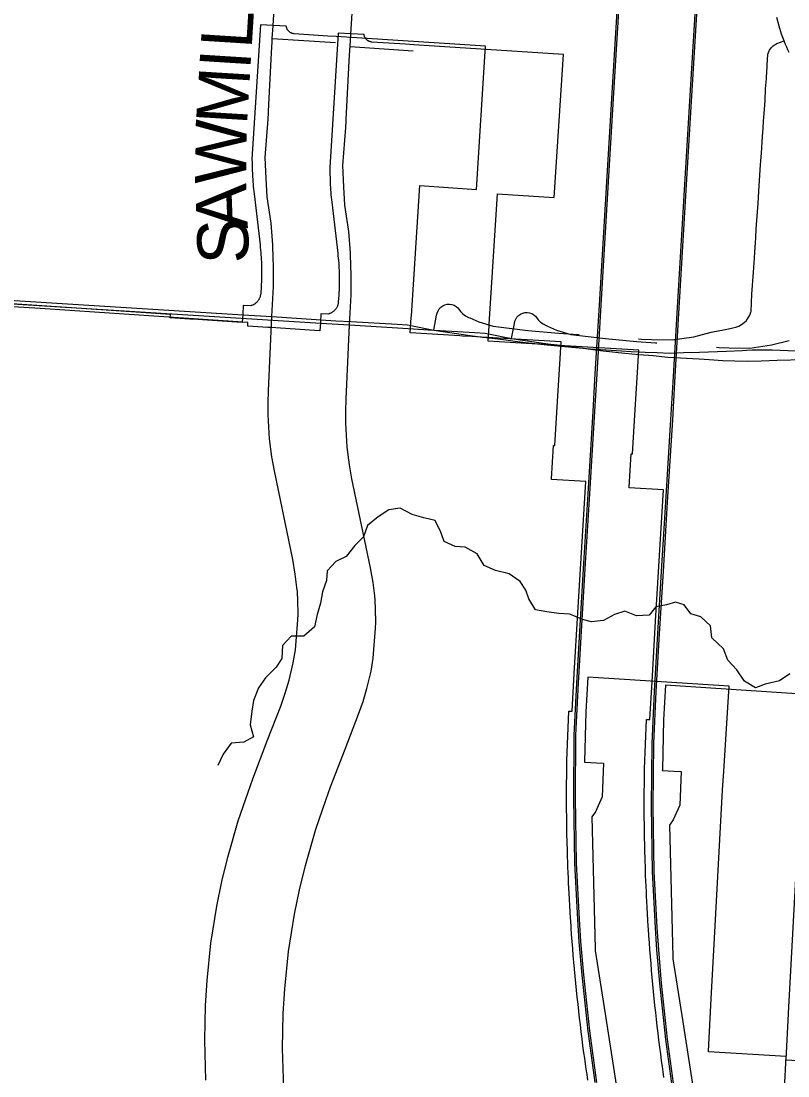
# Model space of a CAD drawing. Extents: x -38.2 to 41.9, y -4 to 24.9.
# Drawn here: x 5.806 to 6.659, y 19.427 to 20.6 of the extents above; entities that cross this region are included whole.
import ezdxf

# ---------------------------------------------------------------- set-up
doc = ezdxf.new("R2010")
doc.units = 0
for name, color, linetype in [('Default', 7, 'Continuous'), ('GM_X_County_Road', 7, 'Continuous'), ('GM_X_County_Road_Text', 7, 'Continuous'), ('GM_X_Minor_River', 7, 'Continuous'), ('GM_X_Rail_Line', 7, 'Continuous'), ('GM_X_Rail_Line_Text', 7, 'Continuous'), ('GM_X_State_Location', 7, 'Continuous'), ('GM_X_Township_Road', 7, 'Continuous'), ('GM_X_Township_Road_Text', 7, 'Continuous')]:
    doc.layers.add(name, color=color, linetype=linetype)

msp = doc.modelspace()

# ---------------------------------------------------------------- linework, layer by layer
at = {"layer": 'Default'}
for points in [[(6.4368, 19.422), (6.4359, 19.4282), (6.435, 19.4343), (6.4341, 19.4404), (6.4333, 19.4465), (6.4325, 19.4526), (6.4314, 19.4603), (6.4304, 19.4681), (6.4295, 19.4758), (6.4285, 19.4835), (6.4276, 19.4912), (6.4267, 19.499), (6.4259, 19.5067), (6.425, 19.5144), (6.4242, 19.5222), (6.4234, 19.5299), (6.4227, 19.5377), (6.422, 19.5454), (6.4213, 19.5532), (6.4206, 19.5609), (6.42, 19.5687), (6.4194, 19.5764), (6.4188, 19.5842), (6.4183, 19.592), (6.4177, 19.5997), (6.4176, 19.6023), (6.4171, 19.6093), (6.4167, 19.6162), (6.4163, 19.6232), (6.416, 19.6302), (6.4157, 19.6357), (6.4154, 19.6413), (6.4152, 19.6469), (6.4149, 19.653), (6.4147, 19.6591), (6.4144, 19.6653), (6.4143, 19.6697), (6.4141, 19.6742), (6.414, 19.6797), (6.4139, 19.6845), (6.4137, 19.6892), (6.4136, 19.6939), (6.4134, 19.7004), (6.4131, 19.7378), (6.4134, 19.7752), (6.4135, 19.7775), (6.4155, 19.8326), (6.4193, 19.8324), (6.4217, 19.8744), (6.4257, 19.9418), (6.4346, 20.0881), (6.3963, 20.0904), (6.3964, 20.0911), (6.3986, 20.1282), (6.4001, 20.1281), (6.4037, 20.1894), (6.4051, 20.2126), (6.407, 20.2434), (6.3183, 20.2487), (6.3076, 20.2493), (6.2973, 20.2499), (6.2945, 20.2501), (6.2639, 20.2518), (6.2393, 20.2533), (6.2404, 20.2705), (6.2405, 20.2722), (6.2498, 20.4174), (6.313, 20.4131), (6.3231, 20.5724), (6.1569, 20.583), (6.1476, 20.5836), (6.1101, 20.5862), (6.1096, 20.5862), (6.1091, 20.5863), (6.1086, 20.5864), (6.108, 20.5865), (6.1075, 20.5867), (6.107, 20.5869), (6.1066, 20.5871), (6.1061, 20.5874), (6.1056, 20.5876), (6.1052, 20.5879), (6.1048, 20.5883), (6.1044, 20.5886), (6.104, 20.589), (6.1036, 20.5894), (6.1033, 20.5898), (6.103, 20.5902), (6.1027, 20.5907), (6.1024, 20.5911), (6.1022, 20.5916), (6.1019, 20.5921), (6.1018, 20.5926), (6.1016, 20.5931), (6.1015, 20.5936), (6.1013, 20.5947), (6.0726, 20.5961), (6.0631, 20.4466), (6.0632, 20.4433), (6.0633, 20.4395), (6.0635, 20.4348), (6.0637, 20.4301), (6.0637, 20.4299), (6.0638, 20.4272), (6.0639, 20.4244), (6.0641, 20.4217), (6.0643, 20.419), (6.0645, 20.4163), (6.0648, 20.4135), (6.0651, 20.4108), (6.0654, 20.4081), (6.0721, 20.3512), (6.0724, 20.3485), (6.0726, 20.3458), (6.0729, 20.343), (6.0731, 20.3403), (6.0733, 20.3376), (6.0734, 20.3349), (6.0736, 20.3321), (6.0737, 20.3294), (6.0737, 20.3267), (6.0738, 20.3239), (6.0738, 20.3212), (6.0738, 20.3185), (6.0737, 20.3158), (6.0737, 20.313), (6.0736, 20.3103), (6.0734, 20.3076), (6.0733, 20.3048), (6.0728, 20.2968), (6.0727, 20.2962), (6.0726, 20.2955), (6.0724, 20.2948), (6.0723, 20.2942), (6.0721, 20.2935), (6.0719, 20.2929), (6.0716, 20.2922), (6.0713, 20.2916), (6.071, 20.291), (6.0707, 20.2904), (6.0703, 20.2898), (6.0699, 20.2893), (6.0695, 20.2887), (6.0691, 20.2882), (6.0686, 20.2877), (6.0682, 20.2872), (6.0677, 20.2868), (6.0672, 20.2863), (6.0666, 20.2859), (6.0661, 20.2855), (6.0655, 20.2852), (6.0649, 20.2848), (6.0643, 20.2845), (6.0637, 20.2842), (6.0631, 20.284), (6.0624, 20.2837), (6.0618, 20.2835), (6.0617, 20.2835), (6.0533, 20.2838), (6.0528, 20.2743), (6.0521, 20.2648), (6.0463, 20.2652), (5.9975, 20.2685), (5.9941, 20.2687), (5.972, 20.2702), (5.9723, 20.274), (5.7408, 20.2896)], [(6.6556, 19.4121), (6.6576, 19.4485), (6.5709, 19.4535), (6.5709, 19.4542), (6.574, 19.5125), (6.5777, 19.5802), (6.5865, 19.7446), (6.588, 19.7657), (6.594, 19.8602), (6.4368, 19.8705), (6.4345, 19.832), (6.4332, 19.7767), (6.4332, 19.7759), (6.4463, 19.7751), (6.4541, 19.7746), (6.4527, 19.7373), (6.4453, 19.7207), (6.4412, 19.715), (6.4448, 19.5684), (6.445, 19.5662), (6.4559, 19.496), (6.491, 19.2712)]]:
    msp.add_lwpolyline(points, dxfattribs=at)
at = {"layer": 'GM_X_County_Road'}
for p, q in [((6.0866, 20.5949), (6.0898, 20.6465)), ((6.0533, 20.2735), (6.0851, 20.2715))]:
    msp.add_line(p, q, dxfattribs=at)
for points in [[(6.0855, 20.5772), (6.0857, 20.581), (6.0866, 20.5949)], [(6.6607, 20.5655), (6.6594, 20.5684), (6.6581, 20.5712), (6.6568, 20.5741), (6.6556, 20.5771), (6.6551, 20.5783), (6.6545, 20.58), (6.6524, 20.5859), (6.6497, 20.5946), (6.6472, 20.6042)], [(6.5215, 19.4251), (6.5206, 19.4312), (6.5198, 19.4373), (6.5189, 19.4434), (6.5179, 19.4512), (6.5169, 19.4589), (6.5159, 19.4666), (6.515, 19.4743), (6.5141, 19.4821), (6.5132, 19.4898), (6.5123, 19.4975), (6.5115, 19.5053), (6.5107, 19.513), (6.5099, 19.5207), (6.5092, 19.5285), (6.5085, 19.5362), (6.5078, 19.544), (6.5071, 19.5517), (6.5065, 19.5595), (6.5059, 19.5673), (6.5053, 19.575), (6.5047, 19.5828), (6.5042, 19.5905), (6.504, 19.5931), (6.5036, 19.6001), (6.5032, 19.607), (6.5028, 19.614), (6.5024, 19.621), (6.5021, 19.6266), (6.5019, 19.6321), (6.5016, 19.6377), (6.5014, 19.6438), (6.5011, 19.6499), (6.5009, 19.6561), (6.5008, 19.6605), (6.5006, 19.665), (6.5005, 19.6705), (6.5003, 19.6753), (6.5002, 19.68), (6.5001, 19.6847), (6.4999, 19.6912), (6.4995, 19.7286), (6.4999, 19.766), (6.5, 19.7683), (6.502, 19.8234), (6.5057, 19.8233), (6.5082, 19.8652), (6.5122, 19.9326), (6.521, 20.0789), (6.4828, 20.0812), (6.4829, 20.0819), (6.4851, 20.119), (6.4866, 20.1189), (6.4902, 20.1802), (6.4916, 20.2035), (6.4934, 20.2342), (6.4048, 20.2395), (6.3941, 20.2401), (6.3838, 20.2408), (6.3809, 20.2409), (6.3504, 20.2426), (6.3258, 20.2442), (6.3269, 20.2613), (6.327, 20.263), (6.3363, 20.4082), (6.3995, 20.4039), (6.4096, 20.5632), (6.2433, 20.5738), (6.2341, 20.5745), (6.1966, 20.577), (6.1961, 20.577), (6.1956, 20.5771), (6.195, 20.5772), (6.1945, 20.5774), (6.194, 20.5775), (6.1935, 20.5777), (6.193, 20.5779), (6.1926, 20.5782), (6.1921, 20.5785), (6.1917, 20.5788), (6.1912, 20.5791), (6.1908, 20.5794), (6.1905, 20.5798), (6.1901, 20.5802), (6.1897, 20.5806), (6.1894, 20.581), (6.1891, 20.5815), (6.1889, 20.5819), (6.1886, 20.5824), (6.1884, 20.5829), (6.1882, 20.5834), (6.1881, 20.5839), (6.188, 20.5844), (6.1878, 20.5855), (6.1591, 20.5869), (6.1496, 20.4374), (6.1497, 20.4341), (6.1498, 20.4303), (6.15, 20.4256), (6.1501, 20.4209), (6.1501, 20.4207), (6.1503, 20.418), (6.1504, 20.4153), (6.1506, 20.4125), (6.1508, 20.4098), (6.151, 20.4071), (6.1513, 20.4044), (6.1516, 20.4016), (6.1519, 20.3989), (6.1585, 20.342), (6.1588, 20.3393), (6.1591, 20.3366), (6.1594, 20.3338), (6.1596, 20.3311), (6.1598, 20.3284), (6.1599, 20.3257), (6.1601, 20.3229), (6.1602, 20.3202), (6.1602, 20.3175), (6.1603, 20.3148), (6.1603, 20.312), (6.1603, 20.3093), (6.1602, 20.3066), (6.1601, 20.3038), (6.16, 20.3011), (6.1599, 20.2984), (6.1597, 20.2957), (6.1592, 20.2876), (6.1592, 20.287), (6.159, 20.2863), (6.1589, 20.2856), (6.1587, 20.285), (6.1586, 20.2843), (6.1583, 20.2837), (6.1581, 20.283), (6.1578, 20.2824), (6.1575, 20.2818), (6.1572, 20.2812), (6.1568, 20.2807), (6.1564, 20.2801), (6.156, 20.2796), (6.1556, 20.279), (6.1551, 20.2785), (6.1546, 20.278), (6.1541, 20.2776), (6.1536, 20.2771), (6.1531, 20.2767), (6.1525, 20.2763), (6.152, 20.276), (6.1514, 20.2756), (6.1508, 20.2753), (6.1502, 20.275), (6.1495, 20.2748), (6.1489, 20.2746), (6.1482, 20.2744), (6.1482, 20.2743), (6.1398, 20.2746), (6.1392, 20.2651), (6.1386, 20.2556), (6.1328, 20.256), (6.084, 20.2593), (6.0806, 20.2595), (6.0585, 20.261), (6.0587, 20.2648), (5.8273, 20.2804), (5.7607, 20.2848)], [(6.0814, 20.4982), (6.0815, 20.5), (6.0847, 20.5648), (6.0855, 20.5772)], [(6.0863, 20.3505), (6.0862, 20.3515), (6.0843, 20.3753), (6.0801, 20.4047), (6.0788, 20.4251), (6.0778, 20.4487), (6.081, 20.491), (6.0814, 20.4982)], [(6.0851, 20.2715), (6.087, 20.3049), (6.0871, 20.3264), (6.0864, 20.3496), (6.0863, 20.3505)], [(5.3465, 20.3178), (5.3586, 20.3172), (5.4553, 20.3108), (6.0533, 20.2735)], [(6.0119, 19.4219), (6.0105, 19.4664), (6.0113, 19.5053), (6.0131, 19.533), (6.0175, 19.5745), (6.024, 19.6158), (6.0296, 19.6431), (6.0361, 19.6702), (6.0477, 19.7106), (6.0589, 19.7426), (6.0641, 19.7574), (6.0802, 19.7994), (6.0952, 19.8382), (6.1002, 19.8525), (6.1045, 19.8669), (6.1091, 19.8864), (6.1115, 19.9008), (6.114, 19.9342), (6.1145, 19.9406), (6.1142, 19.9552), (6.1136, 19.9652), (6.1132, 19.9702), (6.1113, 19.985), (6.1084, 20.0012), (6.088, 20.1001), (6.0851, 20.1157), (6.0827, 20.1356), (6.0812, 20.1623), (6.0811, 20.1756), (6.0815, 20.189), (6.0851, 20.2715)], [(6.0851, 20.2715), (6.1564, 20.2669), (6.1732, 20.266)], [(6.1732, 20.266), (6.2246, 20.2632), (6.236, 20.2624), (6.2399, 20.2616)], [(6.2399, 20.2616), (6.2653, 20.2564), (6.3058, 20.2504), (6.3197, 20.2488)], [(6.3197, 20.2488), (6.3237, 20.2483), (6.343, 20.2461), (6.3586, 20.2438)], [(6.3586, 20.2438), (6.3674, 20.2426), (6.3914, 20.24), (6.4072, 20.2386)], [(6.4072, 20.2386), (6.4229, 20.2372), (6.4392, 20.2357), (6.4744, 20.2336), (6.4851, 20.2328), (6.5004, 20.2318), (6.5138, 20.2315), (6.5278, 20.231), (6.5432, 20.2315), (6.5611, 20.2321), (6.5911, 20.2331), (6.6084, 20.2337), (6.6132, 20.2341)], [(6.6132, 20.2341), (6.6198, 20.2346), (6.6283, 20.2346), (6.6418, 20.2346), (6.6596, 20.2338), (6.6778, 20.2331), (6.6901, 20.2325), (6.7082, 20.2325), (6.7252, 20.2325), (6.7314, 20.2322), (6.8037, 20.228), (6.9442, 20.2197), (7.074, 20.2124)], [(6.742, 19.4029), (6.7441, 19.4393), (6.6573, 19.4443), (6.6574, 19.445), (6.6605, 19.5033), (6.6642, 19.571), (6.673, 19.7355), (6.6745, 19.7565), (6.6805, 19.851), (6.5233, 19.8614), (6.521, 19.8228), (6.5197, 19.7675), (6.5196, 19.7667), (6.5328, 19.7659), (6.5406, 19.7654), (6.5391, 19.7281), (6.5317, 19.7115), (6.5277, 19.7058), (6.5313, 19.5593), (6.5314, 19.557), (6.5424, 19.4868), (6.5775, 19.262)]]:
    msp.add_lwpolyline(points, dxfattribs=at)
at = {"layer": 'GM_X_Minor_River'}
for points in [[(6.6614, 19.8741), (6.65, 19.8665), (6.6341, 19.8627), (6.6232, 19.8586), (6.6111, 19.8661), (6.6027, 19.8786), (6.5925, 19.8893), (6.5876, 19.9018), (6.5747, 19.9143), (6.5732, 19.9275), (6.5626, 19.9374), (6.5512, 19.9408), (6.544, 19.951), (6.5342, 19.9537), (6.5244, 19.9507), (6.5126, 19.9488), (6.5051, 19.9393), (6.4911, 19.9385), (6.4778, 19.9438), (6.4665, 19.9401), (6.4544, 19.9336), (6.4407, 19.9321), (6.4309, 19.9344), (6.4169, 19.9404), (6.4044, 19.9412), (6.3912, 19.9431), (6.3787, 19.9454), (6.3711, 19.9575), (6.3677, 19.9673), (6.3616, 19.9768), (6.3491, 19.9852), (6.334, 19.989), (6.3215, 19.9946), (6.3136, 20.0075), (6.3003, 20.0151), (6.2893, 20.0159), (6.2768, 20.0215), (6.2734, 20.0318), (6.267, 20.0447), (6.2545, 20.0477), (6.2413, 20.0515), (6.228, 20.0583), (6.2155, 20.0564), (6.2034, 20.0488), (6.1917, 20.039), (6.1871, 20.0265), (6.1777, 20.017), (6.1678, 20.0045), (6.1565, 19.9992), (6.1467, 19.9886), (6.1459, 19.978), (6.1417, 19.9655), (6.1395, 19.9526), (6.1357, 19.9401), (6.1327, 19.9265), (6.1209, 19.9159), (6.1069, 19.9159), (6.0971, 19.9056), (6.0963, 19.8912), (6.0899, 19.8814), (6.0782, 19.8697)], [(6.0782, 19.8697), (6.0702, 19.8587), (6.0649, 19.8443), (6.0631, 19.8325), (6.0612, 19.8174), (6.065, 19.8041), (6.054, 19.7981), (6.04, 19.7969), (6.0309, 19.7848), (6.0252, 19.7723)]]:
    msp.add_lwpolyline(points, dxfattribs=at)
at = {"layer": 'GM_X_Rail_Line'}
for points in [[(6.4449, 19.4193), (6.4372, 19.4766), (6.4303, 19.539), (6.4272, 19.5761), (6.4256, 19.6009), (6.4222, 19.6634), (6.4211, 19.7361), (6.4217, 19.8058), (6.4244, 19.8639), (6.4283, 19.9279), (6.4324, 19.9973), (6.4371, 20.0745), (6.4428, 20.1661), (6.4451, 20.2079), (6.4497, 20.2844), (6.4576, 20.4153), (6.4635, 20.5143), (6.4726, 20.6662)], [(6.4468, 19.4196), (6.439, 19.4768), (6.4322, 19.5392), (6.4291, 19.5763), (6.4275, 19.601), (6.4241, 19.6634), (6.423, 19.7361), (6.4236, 19.8057), (6.4263, 19.8638), (6.4302, 19.9278), (6.4343, 19.9972), (6.439, 20.0744), (6.4447, 20.166), (6.447, 20.2078), (6.4516, 20.2843), (6.4595, 20.4152), (6.4654, 20.5142), (6.4745, 20.6661)]]:
    msp.add_lwpolyline(points, dxfattribs=at)
at = {"layer": 'GM_X_Rail_Line_Text'}
for points in [[(6.5313, 19.4101), (6.5236, 19.4674), (6.5168, 19.5298), (6.5137, 19.5669), (6.5121, 19.5917), (6.5087, 19.6542), (6.5076, 19.7269), (6.5082, 19.7966), (6.5109, 19.8547), (6.5147, 19.9188), (6.5189, 19.9881), (6.5236, 20.0653), (6.5293, 20.1569), (6.5316, 20.1987), (6.5362, 20.2752), (6.5441, 20.4061), (6.55, 20.5051), (6.559, 20.657)], [(6.5332, 19.4104), (6.5255, 19.4676), (6.5187, 19.53), (6.5156, 19.5671), (6.514, 19.5918), (6.5106, 19.6542), (6.5095, 19.7269), (6.5101, 19.7965), (6.5128, 19.8546), (6.5166, 19.9186), (6.5208, 19.988), (6.5255, 20.0652), (6.5312, 20.1568), (6.5335, 20.1986), (6.5381, 20.2751), (6.546, 20.406), (6.5519, 20.505), (6.5609, 20.6569)]]:
    msp.add_lwpolyline(points, dxfattribs=at)
at = {"layer": 'GM_X_State_Location'}
msp.add_line((6.1722, 20.5719), (6.2425, 20.5672), dxfattribs=at)
for points in [[(6.3518, 20.2472), (6.3551, 20.264), (6.3556, 20.2663), (6.3565, 20.2687), (6.3579, 20.2709), (6.3597, 20.2728), (6.3619, 20.2743), (6.3643, 20.2754), (6.3668, 20.276), (6.3687, 20.2761), (6.3694, 20.2761), (6.372, 20.2758), (6.3745, 20.2749), (6.3767, 20.2736), (6.3787, 20.2719), (6.3797, 20.2707), (6.3817, 20.268), (6.3843, 20.2654), (6.3872, 20.2633), (6.3904, 20.2615), (6.3919, 20.2609), (6.4019, 20.2565), (6.4178, 20.2517), (6.4565, 20.247), (6.4908, 20.2439), (6.5122, 20.2424), (6.5135, 20.2424)], [(6.5798, 20.2376), (6.5829, 20.2373), (6.5942, 20.2369), (6.617, 20.2365), (6.6413, 20.24), (6.6606, 20.2449)]]:
    msp.add_lwpolyline(points, dxfattribs=at)
at = {"layer": 'GM_X_Township_Road'}
msp.add_line((6.0857, 20.581), (6.156, 20.5763), dxfattribs=at)
for points in [[(6.4933, 20.2467), (6.4964, 20.2465), (6.5078, 20.2461), (6.5305, 20.2457), (6.5548, 20.2492), (6.5741, 20.2541), (6.5838, 20.2559), (6.5901, 20.2572), (6.5981, 20.259), (6.6016, 20.2598), (6.6048, 20.261), (6.6079, 20.2627), (6.6107, 20.2648), (6.6132, 20.2673), (6.6153, 20.2701), (6.617, 20.2731), (6.6182, 20.2764), (6.6184, 20.2773), (6.6194, 20.2966), (6.621, 20.3208), (6.6223, 20.3364), (6.6226, 20.3431), (6.6236, 20.359), (6.6242, 20.369), (6.6256, 20.388), (6.6262, 20.3974), (6.6272, 20.4111), (6.629, 20.4403), (6.6301, 20.4534), (6.6312, 20.4719), (6.6318, 20.4811), (6.6324, 20.4888), (6.6333, 20.5021), (6.6339, 20.5119), (6.6346, 20.5248), (6.6354, 20.5361), (6.6355, 20.5374), (6.6362, 20.5497), (6.6368, 20.5589), (6.6369, 20.5617), (6.6371, 20.5633), (6.6374, 20.5643), (6.6377, 20.5654), (6.639, 20.5681), (6.6407, 20.5705), (6.6428, 20.5727), (6.6453, 20.5744), (6.6471, 20.5753), (6.6551, 20.5783)], [(6.2653, 20.2564), (6.2686, 20.2732), (6.2691, 20.2755), (6.2701, 20.2779), (6.2715, 20.2801), (6.2733, 20.282), (6.2754, 20.2835), (6.2778, 20.2846), (6.2803, 20.2852), (6.2823, 20.2853), (6.2829, 20.2853), (6.2855, 20.2849), (6.288, 20.2841), (6.2902, 20.2828), (6.2922, 20.2811), (6.2932, 20.2799), (6.2953, 20.2772), (6.2978, 20.2746), (6.3007, 20.2724), (6.3039, 20.2707), (6.3055, 20.2701), (6.3154, 20.2657), (6.3313, 20.2609), (6.37, 20.2562), (6.4044, 20.2531), (6.4257, 20.2516), (6.427, 20.2516)]]:
    msp.add_lwpolyline(points, dxfattribs=at)
at = {"layer": 'GM_X_Township_Road_Text'}
for p, q in [((6.173, 20.5857), (6.1763, 20.6374)), ((6.1397, 20.2643), (6.1716, 20.2623))]:
    msp.add_line(p, q, dxfattribs=at)
for points in [[(6.1719, 20.568), (6.1722, 20.5719), (6.173, 20.5857)], [(6.1679, 20.489), (6.168, 20.4908), (6.1712, 20.5556), (6.1719, 20.568)], [(6.1728, 20.3414), (6.1727, 20.3423), (6.1708, 20.3661), (6.1665, 20.3955), (6.1653, 20.4159), (6.1643, 20.4395), (6.1675, 20.4818), (6.1679, 20.489)], [(6.1716, 20.2623), (6.1735, 20.2957), (6.1736, 20.3172), (6.1728, 20.3404), (6.1728, 20.3414)], [(5.4329, 20.3087), (5.445, 20.308), (5.5418, 20.3016), (6.1397, 20.2643)], [(6.0984, 19.4127), (6.097, 19.4572), (6.0978, 19.4961), (6.0995, 19.5238), (6.1039, 19.5653), (6.1105, 19.6066), (6.1161, 19.6339), (6.1226, 19.661), (6.1342, 19.7014), (6.1454, 19.7334), (6.1506, 19.7483), (6.1667, 19.7902), (6.1817, 19.8291), (6.1867, 19.8433), (6.191, 19.8577), (6.1956, 19.8772), (6.198, 19.8916), (6.2005, 19.925), (6.201, 19.9314), (6.2007, 19.946), (6.2001, 19.956), (6.1997, 19.961), (6.1978, 19.9758), (6.1949, 19.9921), (6.1744, 20.0909), (6.1716, 20.1065), (6.1692, 20.1264), (6.1677, 20.1531), (6.1676, 20.1664), (6.1679, 20.1798), (6.1716, 20.2623)], [(6.1716, 20.2623), (6.2428, 20.2578), (6.2597, 20.2568)], [(6.2597, 20.2568), (6.3111, 20.254), (6.3224, 20.2532), (6.3264, 20.2524)], [(6.3264, 20.2524), (6.3518, 20.2472), (6.3923, 20.2412), (6.4062, 20.2396)], [(6.4062, 20.2396), (6.4102, 20.2391), (6.4295, 20.2369), (6.4451, 20.2347)], [(6.4451, 20.2347), (6.4539, 20.2334), (6.4779, 20.2308), (6.4936, 20.2294)], [(6.4936, 20.2294), (6.5094, 20.2281), (6.5257, 20.2265), (6.5608, 20.2244), (6.5716, 20.2237), (6.5869, 20.2226), (6.6003, 20.2223), (6.6143, 20.2218), (6.6297, 20.2223), (6.6476, 20.2229), (6.6775, 20.2239), (6.6949, 20.2246), (6.6996, 20.2249)]]:
    msp.add_lwpolyline(points, dxfattribs=at)

# ---------------------------------------------------------------- texts
at = {"layer": 'GM_X_County_Road_Text'}
for s, rotation, p in [('L', 86.3935, (6.0627, 20.5687)), ('I', 86.3954, (6.0612, 20.5454)), ('M', 86.5097, (6.0575, 20.4839)), ('W', 89.271, (6.0566, 20.4188)), ('A', 92.2226, (6.0586, 20.3696)), ('S', 92.4477, (6.0602, 20.3313))]:
    msp.add_text(s, height=0.0568, rotation=rotation, dxfattribs=at).set_placement(p)

doc.saveas('drawing.dxf')
